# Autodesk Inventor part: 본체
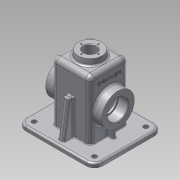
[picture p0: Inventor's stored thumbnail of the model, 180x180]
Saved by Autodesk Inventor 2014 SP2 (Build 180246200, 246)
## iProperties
Created: 2016-08
Part Number: 본체
Material: 알루미늄 6061
Document SubType Name: Modeling
Designer: user
Density: 2.71 g/cm^3
Appearance: 알루미늄 - 평지
Mass: 800.115 g
Surface Area: 912.153 cm^2
Volume: 295.245 cm^3
Author: user
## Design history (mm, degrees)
sketch "스케치1"
  geometry: L1 (-65, 57.5)-(65, 57.5); L2 (65, 57.5)-(65, -57.5); L3 (65, -57.5)-(-65, -57.5); L4 (-65, -57.5)-(-65, 57.5); L5 (-65, 57.5)-(65, -57.5); L6 (65, 57.5)-(-65, -57.5); 3 further points
  constraints: 12 end point, 3 midpoint, 2 parallel, 1 coincident, 1 horizontal alignment, 1 vertical
  dimensions: "d0" = 130 distance of L1.start L1.end; "d1" = 115 distance of L1.end L2.end
extrude "돌출1" new body sketch "스케치1" distance "d2" = 10; taper "d3" = 0 deg
sketch "스케치2"
  geometry: L1 (57.5, 0)-(-57.5, 0) reference; C1 r 27.5 at (0, 55); 2 further points
  constraints: 1 centre point, 1 midpoint, 1 vertical alignment
  dimensions: "d4" = 55 distance from line of L1 C1.centre; "d5" = 55 diameter of C1
extrude "돌출2" join sketch "스케치2" stored distance "d6" = 95; taper "d7" = 0 deg
sketch "스케치4"
  geometry: L1 (-65, 10)-(65, 10) reference; L2 (32.5, 10)-(32.5, 110); L3 (32.5, 110)-(-32.5, 110); L4 (-32.5, 110)-(-32.5, 10); L5 (65, 0)-(65, 10) reference; L6 (-65, 0)-(-65, 10) reference; 1 further point
  constraints: 6 end point, 2 point on line
  dimensions: "d14" = 65 distance of L2.end L3.end; "d15" = 32.5 distance between parallel lines of L5 L2; "d16" = 32.5 distance between parallel lines of L6 L4; "d17" = 100 distance from line of L2.start L3
extrude "돌출4" join sketch "스케치4" stored distance "d18" = 65; taper "d19" = 0 deg
sketch "스케치5"
  geometry: L1 (-42.5, 3)-(42.5, 3); L2 (42.5, 3)-(42.5, -3); L3 (42.5, -3)-(-42.5, -3); L4 (-42.5, -3)-(-42.5, 3); L5 (-42.5, 3)-(42.5, -3); L6 (42.5, 3)-(-42.5, -3); L7 (-65, -57.5)-(-65, 57.5) reference; L8 (65, 57.5)-(65, -57.5) reference; L9 (32.5, 3)-(32.5, -3); L10 (-32.5, -3)-(-32.5, 3); 1 further point
  constraints: 16 end point, 4 point on line, 4 vertical alignment, 2 horizontal alignment, 2 midpoint
  dimensions: "d21" = 6 distance of L3.end L1.start; "d22" = 10 distance between parallel lines of L4 L10; "d23" = 10 distance between parallel lines of L2 L9; "d24" = 22.5 distance between parallel lines of L4 L7
extrude "돌출5" join sketch "스케치5" stored distance "d25" = 65; taper "d26" = 0 deg
sketch "스케치6"
  geometry: L1 (47.5, 27.5)-(47.5, 82.5) reference; L2 (-47.5, 82.5)-(-47.5, 27.5) reference; L3 (65, 0)-(-65, 0) reference; L4 (47.5, 55)-(-47.5, 55); L5 (47.5, 72.5)-(30.5, 72.5); L6 (30.5, 72.5)-(30.5, 70); L7 (30.5, 70)-(-30.5, 70); L8 (-30.5, 70)-(-30.5, 72.5); L9 (-30.5, 72.5)-(-47.5, 72.5); L10 (47.5, 72.5)-(47.5, 55); L11 (-47.5, 55)-(-47.5, 72.5); 1 further point
  constraints: 16 end point, 2 horizontal, 2 midpoint, 2 point on line, 2 vertical, 1 horizontal alignment
  dimensions: "d28" = 35 diameter of L5.start L4; "d29" = 30 diameter of L7 L4; "d30" = 17 distance of L8.end L9.end; "d31" = 17 distance of L5.start L5.end
revolve "회전1" sketch "스케치6" stored, may be unused: angle "d32" = 90 deg
fillet "모깎기1" dims "d33" = 0.3
sketch "스케치7"
  geometry: L1 (65, 0)-(-65, 0) reference; L2 (27.5, 0)-(27.5, 105); L3 (27.5, 105)-(-27.5, 105); L4 (-27.5, 105)-(-27.5, 0); L5 (27.5, 0)-(-27.5, 0); L6 (32.5, 10)-(32.5, 110) reference; L7 (-32.5, 110)-(-32.5, 10) reference; 1 further point
  constraints: 8 end point, 2 point on line, 2 vertical alignment, 1 horizontal alignment
  dimensions: "d34" = 5 distance between parallel lines of L6 L2; "d35" = 5 distance between parallel lines of L7 L4; "d36" = 5 distance from line of L7.start L3
extrude "돌출6" cut sketch "스케치7" stored distance "d37" = 55; taper "d38" = 0 deg
fillet "모깎기2" dims "d39" = 3
fillet "모깎기3" dims "d40" = 3
node "작업 평면1"
sketch "스케치8"
  geometry: C1 r 20 at (32.5, -32.5); 1 further point
  constraints: 1 centre point, 1 coincident
  dimensions: "d42" = 40 diameter of C1
extrude "돌출7" join sketch "스케치8" stored distance "d43" = 55; taper "d44" = 7 deg
hole "구멍1" diameter "d47" = 21; stored, may be unused: countersink angle "d51" = 90 deg, drill point angle "d53" = 0 deg; dims "d45" = 10, "d46" = 10, "d48" = 6, "d49" = 4, "d50" = 2, "d52" = 8
chamfer "모따기1" distance "d54" = 1; stored, may be unused: second distance "d55" = 2, angle "d56" = 45 deg
sketch "스케치9"
  geometry: L1 (57.5, 10)-(-57.5, 10) reference; L2 (-32.5, 110)-(-32.5, 10) reference; L3 (32.5, 10)-(32.5, 110) reference; L4 (-49.5, 10)-(-41.068, 70); L5 (-57.5, 0)-(57.5, 0) reference; L6 (-57.5, 0)-(-57.5, 10) reference; L7 (-41.068, 70)-(-32.5, 70); 1 further point
  constraints: 4 end point, 2 point on line, 1 horizontal alignment
  dimensions: "d58" = 8 deg angle of L6 L4; "d59" = 8 distance from line of L6 L4.start; "d61" = 70 vertical distance of L4.end L5.start
feature "리브1" sketch "스케치9" dims "d62" = 1, "d63" = 10, "d64" = 0, "d65" = 0, "d66" = 1, "d67" = 1
sketch "스케치10"
  geometry: C1 r 2 at (-21, 0); C2 r 2 at (0, 21); C3 r 2 at (0, -21); C4 r 2 at (21, 0); A1 r 21 centre (0, 0) between (-21, 0) and (0, 21); 1 further point
  constraints: 5 centre point, 4 point on circle, 3 equal radius, 2 horizontal alignment, 2 vertical alignment, 1 other
  dimensions: "d68" = 4 diameter of C1; "d69" = 42 diameter of A1
hole "구멍2" sketch "스케치10" at (-21, 0), (0, 21), (21, 0), (0, -21) diameter "d70" = 3.242; stored, may be unused: countersink angle "d74" = 90 deg, drill point angle "d76" = 118 deg; dims "d71" = 8, "d72" = 4, "d73" = 2, "d75" = 10
sketch "스케치11"
  geometry: C1 r 1.5 at (0, 14.5); C2 r 1.5 at (14.5, 0); C3 r 1.5 at (0, -14.5); C4 r 1.5 at (-14.5, 0); A1 r 14.5 centre (0, 0) between (0, 14.5) and (14.5, 0); 1 further point
  constraints: 5 centre point, 4 point on circle, 3 equal radius, 2 horizontal alignment, 2 vertical alignment, 1 coincident
  dimensions: "d77" = 3 diameter of C1; "d78" = 29 diameter of A1
hole "구멍3" sketch "스케치11" at (0, 14.5), (14.5, 0), (0, -14.5), (-14.5, 0) diameter "d79" = 2.459; stored, may be unused: countersink angle "d83" = 90 deg, drill point angle "d85" = 118 deg; dims "d80" = 7, "d81" = 4, "d82" = 2, "d84" = 9
sketch "스케치12"
  geometry: L1 (-10, 12.5)-(-10, 52.5) reference; L2 (100, 0)-(0, 0) reference; 2 further points
  constraints: 1 other
  dimensions: "d86" = 26 distance from line of L1 point (16, 32.5); "d87" = 32.5 distance from line of point (16, 32.5) L2
feature "엠보싱1" sketch "스케치12" dims "d0" = 130, "d1" = 115, "d14" = 65, "d15" = 32.5, "d16" = 32.5, "d17" = 100, "d88" = 0.5, "d89" = 0
fillet "모깎기4" dims "d90" = 14
fillet "모깎기5" dims "d91" = 3
sketch "스케치13"
  geometry: C1 r 4 at (-51, 43.5); C2 r 4 at (51, 43.5); C3 r 4 at (51, -43.5); C4 r 4 at (-51, -43.5); 1 further point
  constraints: 4 centre point, 3 equal radius, 2 horizontal alignment, 2 vertical alignment
  dimensions: "d92" = 8 diameter of C1; "d93" = 102 distance of C2.centre C1.centre; "d94" = 87 distance of C3.centre C2.centre; "d95" = 51 horizontal distance of point (0, 0) C1.centre; "d96" = 43.5 vertical distance of point (0, 0) C2.centre
hole "구멍4" sketch "스케치13" at (-51, 43.5), (51, 43.5), (51, -43.5), (-51, -43.5) diameter "d97" = 8; stored, may be unused: countersink angle "d101" = 90 deg, drill point angle "d103" = 118 deg; dims "d98" = 7, "d99" = 4, "d100" = 2, "d102" = 9
sketch "스케치14"
  geometry: L1 (51, 57.5)-(-51, 57.5) reference; L2 (65, -43.5)-(65, 43.5) reference; L3 (-51, -57.5)-(51, -57.5) reference; L4 (-65, 43.5)-(-65, -43.5) reference; L5 (51, 52.5)-(-51, 52.5); L6 (-60, 43.5)-(-60, -43.5); L7 (-51, -52.5)-(51, -52.5); L8 (60, -43.5)-(60, 43.5); A1 r 14 centre (51, 43.5) between (65, 43.5) and (51, 57.5) reference; A2 r 14 centre (51, -43.5) between (51, -57.5) and (65, -43.5) reference; A3 r 14 centre (-51, -43.5) between (-65, -43.5) and (-51, -57.5) reference; A4 r 14 centre (-51, 43.5) between (-51, 57.5) and (-65, 43.5) reference; A5 r 9 centre (-51, 43.5) between (-51, 52.5) and (-60, 43.5); A6 r 9 centre (-51, -43.5) between (-60, -43.5) and (-51, -52.5); A7 r 9 centre (51, -43.5) between (51, -52.5) and (60, -43.5); A8 r 9 centre (51, 43.5) between (60, 43.5) and (51, 52.5); 1 further point
  constraints: 8 end point, 8 point on circle, 4 centre point, 7 other
  dimensions: "d104" = 5 distance between parallel lines of L4 L6
extrude "돌출8" cut sketch "스케치14" distance "d105" = 3; taper "d106" = 0 deg
fillet "모깎기6" dims "d107" = 8
fillet "모깎기7" dims "d108" = 8
fillet "모깎기8" dims "d109" = 3
fillet "모깎기9" dims "d110" = 3
fillet "모깎기10" dims "d111" = 3
fillet "모깎기11" dims "d112" = 1
node "솔리드1"
mirror "대칭1"
mirror "대칭2"
